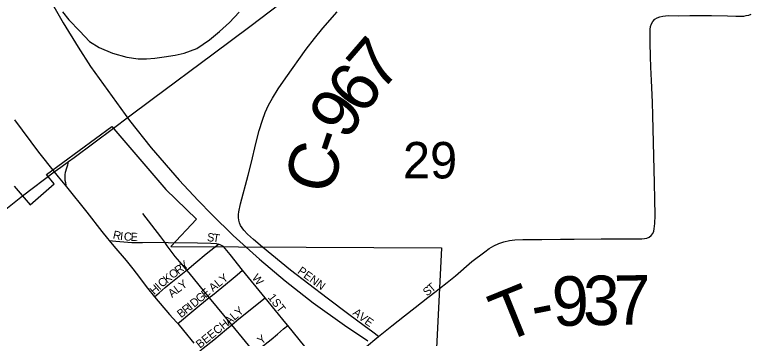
# Model space of a CAD drawing. Extents: x 1874609 to 2204689, y 815661 to 1281160.
# Drawn here: x 2019406 to 2023873, y 968566 to 970528 of the extents above; entities that cross this region are included whole.
import ezdxf

# ---------------------------------------------------------------- set-up
doc = ezdxf.new("R2010")
doc.units = 0
for name, color, linetype in [('GM_X_City_Street', 7, 'Continuous'), ('GM_X_City_Street_Text', 7, 'Continuous'), ('GM_X_Corporation', 7, 'Continuous'), ('GM_X_County_Road', 7, 'Continuous'), ('GM_X_County_Road_Text', 7, 'Continuous'), ('GM_X_Interchange_Ramps', 7, 'Continuous'), ('GM_X_Minor_River', 7, 'Continuous'), ('GM_X_Rail_Line', 7, 'Continuous'), ('GM_X_Section_Text', 7, 'Continuous'), ('GM_X_State_Route', 7, 'Continuous'), ('GM_X_Township_Road', 7, 'Continuous'), ('GM_X_Township_Road_Text', 7, 'Continuous')]:
    doc.layers.add(name, color=color, linetype=linetype)

msp = doc.modelspace()

# ---------------------------------------------------------------- linework, layer by layer
at = {"layer": 'GM_X_City_Street'}
for points in [[(2020315.6, 969148.1), (2020292.1, 969180.4), (2020182.3, 969321.9)], [(2019979.8, 969159.5), (2020019.1, 969155.4), (2020067.9, 969150.2), (2020116.8, 969147.4), (2020182, 969147.4), (2020315.6, 969148.1)], [(2020449.5, 968980.1), (2020421.6, 969012.5), (2020379.9, 969062.7), (2020330.1, 969127.2), (2020315.6, 969148.1)], [(2020315.6, 969148.1), (2020337, 969147.9), (2020514.9, 969145.7), (2020595.3, 969142.9), (2020626.9, 969140.7), (2020642, 969137.8)], [(2020449.5, 968980.1), (2020505.3, 969025.8), (2020567.6, 969077.2), (2020642, 969137.8)], [(2020787.6, 968978.5), (2020712.5, 969074.3), (2020671.3, 969121.8), (2020656.6, 969131.7), (2020642, 969137.8)], [(2021611.2, 968576.9), (2021577.5, 968602.5), (2021525.3, 968642.2), (2021431.9, 968709.8), (2021299.9, 968808.4), (2021078.2, 968979.5), (2020907.8, 969119.6)], [(2020253.4, 968816.5), (2020282.4, 968841.6), (2020318.9, 968873), (2020343.7, 968893.4), (2020443.1, 968974.9), (2020449.5, 968980.1)], [(2020586.3, 968812.5), (2020464.3, 968963), (2020449.5, 968980.1)], [(2020586.3, 968812.5), (2020604.9, 968827.1), (2020718.5, 968921), (2020755.3, 968951.3), (2020787.6, 968978.5)], [(2020925, 968812.3), (2020787.6, 968978.5)], [(2021611.2, 968576.9), (2021692.1, 968641.6), (2021769.7, 968702.1), (2021833.8, 968752.9), (2021910.4, 968813.6), (2021961.9, 968852.4), (2021982.3, 968867.7)], [(2020394.4, 968655.1), (2020416.9, 968673.8), (2020467.7, 968716), (2020529, 968767.6), (2020586.3, 968812.5)], [(2020722.1, 968647.2), (2020587.8, 968810.7), (2020586.3, 968812.5)], [(2020722.1, 968647.2), (2020753.8, 968673.1), (2020856.8, 968756.5), (2020925, 968812.3)], [(2021061.4, 968644.3), (2021050.1, 968658.1), (2020925, 968812.3)], [(2020529.1, 968490.4), (2020548.7, 968506), (2020613.4, 968557.2), (2020689.7, 968620.7), (2020722.1, 968647.2)], [(2020859.5, 968479.3), (2020804.7, 968546.8), (2020722.1, 968647.2)], [(2020859.5, 968479.3), (2020896.6, 968508.1), (2020960.8, 968559), (2020998.7, 968590.5), (2021036.1, 968622.5), (2021061.4, 968644.3)], [(2021200, 968474.6), (2021061.4, 968644.3)], [(2021501.3, 968483.3), (2021552.1, 968527), (2021589.4, 968559.4), (2021611.2, 968576.9)]]:
    msp.add_lwpolyline(points, dxfattribs=at)
at = {"layer": 'GM_X_Corporation'}
msp.add_lwpolyline([(2019402.8, 969489), (2019500.4, 969375), (2019644.4, 969502.8), (2019598.8, 969559.9), (2019995.6, 969851.1), (2020323.4, 969468.5), (2020507.7, 969287.9), (2020353.4, 969121.8), (2021994.3, 969114.6), (2021940.5, 968020.4)], dxfattribs=at)
at = {"layer": 'GM_X_County_Road'}
msp.add_lwpolyline([(2020907.8, 969119.6), (2020854.8, 969164.9), (2020818.2, 969198.1), (2020795.3, 969222), (2020784.9, 969235.3), (2020776.2, 969249.9), (2020769.5, 969265.7), (2020765.4, 969282.3), (2020763.7, 969299.2), (2020764, 969316.1), (2020765.8, 969332.8), (2020775.5, 969381.4), (2020821.3, 969555.8), (2020841.3, 969635.1), (2020867.9, 969746.5), (2020889.4, 969825.6), (2020908.8, 969888.2), (2020925.5, 969934.5), (2020945.4, 969979.7), (2020968.7, 970023.1), (2021003.2, 970078.9), (2021050, 970146.1), (2021173.5, 970319), (2021223.5, 970383.8), (2021275.6, 970446.9), (2021361.8, 970545.5)], dxfattribs=at)
at = {"layer": 'GM_X_Interchange_Ramps'}
msp.add_lwpolyline([(2019719.5, 969484.2), (2019715.6, 969507.9), (2019713, 969523.8), (2019711.5, 969540.5), (2019712.2, 969557.3), (2019714.9, 969573.8), (2019721.9, 969599), (2019727.9, 969617.1), (2019729.8, 969625.9), (2019733.1, 969638.6)], dxfattribs=at)
at = {"layer": 'GM_X_Minor_River'}
msp.add_lwpolyline([(2019696.7, 970546.6), (2019734.7, 970496.5), (2019800.8, 970428.3), (2019858.9, 970366.1), (2019918.9, 970329.9), (2019999.1, 970295.8), (2020085.2, 970271.7), (2020155.4, 970261.7), (2020205.5, 970261.6), (2020255.6, 970265.6), (2020311.7, 970273.6), (2020379.9, 970283.6), (2020434, 970295.6), (2020510.2, 970323.6), (2020586.4, 970375.7), (2020648.6, 970425.8), (2020708.8, 970481.9), (2020767, 970544)], dxfattribs=at)
at = {"layer": 'GM_X_Rail_Line'}
msp.add_lwpolyline([(2019597.3, 970662.1), (2019699.6, 970479.5), (2019790.9, 970331.3), (2019866.7, 970214.5), (2020101.6, 969886.3), (2020233.4, 969720.6), (2020402.7, 969525.6), (2020518.4, 969401.1), (2020602.3, 969317), (2020731.6, 969189.8), (2020890, 969045.7), (2021045.4, 968915.3), (2021216.4, 968780.5), (2021406.8, 968644.6), (2021547.8, 968550.1)], dxfattribs=at)
at = {"layer": 'GM_X_State_Route'}
for points in [[(2020004.5, 969840.2), (2020096.6, 969908.6), (2020240.6, 970017.2), (2020608.9, 970291.3), (2020832.5, 970457.8), (2021016, 970595.7)], [(2019405, 969891.2), (2019549.4, 969695), (2019645.7, 969574.9)], [(2019334.5, 969333.3), (2019351.6, 969348.8), (2019453.7, 969429), (2019645.7, 969574.9), (2019686.3, 969604.7), (2019733.1, 969638.6), (2019766.7, 969663.1), (2020004.5, 969840.2)], [(2019645.7, 969574.9), (2019669.2, 969546.1)], [(2019669.2, 969546.1), (2019719.5, 969484.2), (2019842.9, 969330.9), (2019934.6, 969214.6), (2019969.7, 969171.7)], [(2019969.7, 969171.7), (2019979.8, 969159.5), (2020007.7, 969125.5), (2020081.1, 969036.9), (2020122, 968986.3), (2020141.7, 968960.5), (2020211.2, 968869.9), (2020253.4, 968816.5), (2020344.4, 968711), (2020387.5, 968663.1), (2020394.4, 968655.1), (2020430.2, 968613.5), (2020492.9, 968537.2)]]:
    msp.add_lwpolyline(points, dxfattribs=at)
at = {"layer": 'GM_X_Township_Road'}
msp.add_lwpolyline([(2021982.3, 968867.7), (2022027.6, 968904.1), (2022078.1, 968945.5), (2022177.9, 969030.8), (2022256, 969090.7), (2022283, 969109.7), (2022311.5, 969126.4), (2022341.7, 969140.2), (2022373.1, 969151), (2022405.6, 969158.4), (2022438.5, 969162.5), (2022488, 969164.4), (2022553.6, 969164.4), (2022602.6, 969164.6), (2022716.8, 969166.6), (2022798.8, 969167.9), (2022962.9, 969169.5), (2023094.3, 969169.3), (2023159.7, 969168.3), (2023208.7, 969169.9), (2023224.8, 969171.2), (2023240.2, 969174.1), (2023254.2, 969180), (2023265.9, 969189), (2023275, 969201), (2023280.9, 969215), (2023284.8, 969230.4), (2023288.7, 969262.4), (2023290.4, 969311.3), (2023288.4, 969409.4), (2023286.6, 969507.8), (2023282.5, 969670.9), (2023280.3, 969752.9), (2023276.4, 969916.9), (2023273.7, 969998.6), (2023267.4, 970129.2), (2023264.6, 970210.9), (2023262.5, 970276), (2023260.2, 970357.5), (2023258.8, 970423.1), (2023259.3, 970439.8), (2023261.7, 970456.7), (2023267.2, 970473.1), (2023276.1, 970488.1), (2023288.3, 970500.6), (2023302.8, 970510), (2023318.9, 970516.4), (2023335.6, 970520.2), (2023369, 970522.8), (2023434.3, 970522.3), (2023499.8, 970523.5), (2023532.5, 970524.3), (2023631, 970524.3), (2023729.5, 970522), (2023778.4, 970520), (2023810.8, 970519.6), (2023826.7, 970520.6), (2023842.4, 970523), (2023857.8, 970526.5), (2023872.7, 970531.8)], dxfattribs=at)

# ---------------------------------------------------------------- texts
at = {"layer": 'GM_X_City_Street_Text'}
for s, rotation, p in [('R', 347.4422, (2019998.2, 969172)), ('I', 354.071, (2020043.1, 969162.4)), ('C', 355.2704, (2020066.2, 969160)), ('E', 358.0963, (2020108.3, 969156.6)), ('S', 354.9119, (2020570.9, 969155.2)), ('T', 351.2788, (2020605.1, 969152.2)), ('Y', 38.5937, (2020431.6, 968975.6)), ('O', 37.4207, (2020364.3, 968924.1)), ('R', 37.3895, (2020399.2, 968950.8)), ('PENN', 324.0898, (2021117.1, 968964.3)), ('K', 38.4789, (2020330, 968896.9)), ('ALY', 39.2878, (2020608.4, 968845.1)), ('W', 308.6625, (2020841.7, 968931.7)), ('I', 41.7533, (2020284.5, 968856.5)), ('C', 41.3573, (2020300.8, 968871.1)), ('Y', 35.9518, (2020422.1, 968858.6)), ('T', 40.7503, (2021934.5, 968841.9)), ('H', 41.7679, (2020251.7, 968827.2)), ('A', 39.0864, (2020360.3, 968810.3)), ('L', 36.7606, (2020394.1, 968837.7)), ('E', 40.8957, (2020563, 968807.9)), ('S', 39.5047, (2021906.4, 968818.8)), ('D', 39.1529, (2020494.2, 968750.4)), ('G', 40.6674, (2020529.5, 968779.1)), ('1ST', 307.8725, (2020938.6, 968812.8)), ('R', 38.6876, (2020445.8, 968711.6)), ('I', 38.7003, (2020476.7, 968736.4)), ('ALY', 41.0114, (2020704.7, 968642.3)), ('B', 38.6863, (2020414.9, 968686.8)), ('A', 322.3608, (2021451.8, 968713.3)), ('V', 322.3435, (2021486.6, 968686.4)), ('BEECH', 38.854, (2020529.5, 968502.2)), ('E', 324.6531, (2021523.2, 968658.2)), ('Y', 39.711, (2020902.4, 968525.6))]:
    msp.add_text(s, height=50, rotation=rotation, dxfattribs=at).set_placement(p)
at = {"layer": 'GM_X_County_Road_Text'}
for s, rotation, p in [('7', 49.2429, (2021625.7, 970052.7)), ('6', 53.6287, (2021519.9, 969908.6)), ('9', 55.786, (2021417.7, 969758.2)), ('-', 71.254, (2021387.7, 969660.7)), ('C', 75.2604, (2021326.6, 969427.7))]:
    msp.add_text(s, height=300, rotation=rotation, dxfattribs=at).set_placement(p)
at = {"layer": 'GM_X_Section_Text'}
msp.add_text('29', height=221, rotation=0, dxfattribs=at).set_placement((2021760.5, 969535.6))
at = {"layer": 'GM_X_Township_Road_Text'}
for s, rotation, p in [('9', 2.6028, (2022671.5, 968637.3)), ('3', 0.2394, (2022852.8, 968645.6)), ('7', 1.0427, (2023042.2, 968646.4)), ('T', 22.0218, (2022368.7, 968535)), ('-', 11.1553, (2022562.4, 968614.9))]:
    msp.add_text(s, height=300, rotation=rotation, dxfattribs=at).set_placement(p)

doc.saveas('drawing.dxf')
